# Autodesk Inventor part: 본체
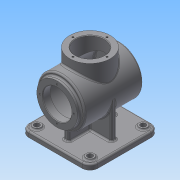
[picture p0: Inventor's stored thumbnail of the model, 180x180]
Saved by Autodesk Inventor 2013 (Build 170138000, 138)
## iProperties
Created: 2015-07
Part Number: 본체
Material: 일반
Document SubType Name: Modeling
Designer: Administrator
Density: 1 g/cm^3
Author: Administrator
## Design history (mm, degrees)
sketch "스케치1"
  geometry: L1 (-50, -65)-(50, -65); L2 (65, -50)-(65, 50); L3 (50, 65)-(-50, 65); L4 (-65, 50)-(-65, -50); L5 (-65, -65)-(65, 65); L6 (65, -65)-(-65, 65); C1 r 7.5 at (-50, 50); C2 r 7.5 at (50, 50); C3 r 7.5 at (-50, -50); C4 r 7.5 at (50, -50); A1 r 15 centre (-50, 50) between (-50, 65) and (-65, 50); A2 r 15 centre (-50, -50) between (-65, -50) and (-50, -65); A3 r 15 centre (50, -50) between (50, -65) and (65, -50); A4 r 15 centre (50, 50) between (65, 50) and (50, 65); 3 further points
  constraints: 12 end point, 8 centre point, 8 point on circle, 8 point on line, 8 tangent, 5 equal radius, 3 midpoint, 2 horizontal alignment, 2 parallel, 2 vertical alignment, 1 coincident, 1 horizontal, 1 perpendicular
  dimensions: "d0" = 130 distance of L5.end L6.end; "d2" = 130 distance of L6.start L5.end; "d3" = 15 radius of A1; "d4" = 15 diameter of C1; "d5" = 15 diameter of C2; "d6" = 100 distance of C2.centre C1.centre; "d7" = 50 horizontal distance of point (0, 0) C1.centre; "d8" = 100 distance of C3.centre C1.centre; "d9" = 50 horizontal distance of C1.centre point (0, 0)
extrude "돌출1" new body sketch "스케치1" distance "d10" = 10; taper "d11" = 0 deg
extrude "돌출2" join sketch "스케치1" distance "d12" = 3; taper "d13" = 0 deg
hole "구멍1" diameter "d16" = 10; stored, may be unused: countersink angle "d20" = 90 deg, drill point angle "d22" = 0 deg; dims "d14" = 10, "d15" = 10, "d17" = 6, "d18" = 4, "d19" = 2, "d21" = 8
hole "구멍2" diameter "d25" = 10; stored, may be unused: countersink angle "d29" = 90 deg, drill point angle "d31" = 0 deg; dims "d23" = 10, "d24" = 10, "d26" = 6, "d27" = 4, "d28" = 2, "d30" = 8
hole "구멍3" diameter "d34" = 10; stored, may be unused: countersink angle "d38" = 90 deg, drill point angle "d40" = 0 deg; dims "d32" = 10, "d33" = 10, "d35" = 6, "d36" = 4, "d37" = 2, "d39" = 8
hole "구멍4" diameter "d43" = 10; stored, may be unused: countersink angle "d47" = 90 deg, drill point angle "d49" = 0 deg; dims "d41" = 10, "d42" = 10, "d44" = 6, "d45" = 4, "d46" = 2, "d48" = 8
sketch "스케치2"
  geometry: L1 (50, -10)-(-50, -10) reference; C1 r 45 at (0, 68); 1 further point
  constraints: 1 centre point
  dimensions: "d51" = 90 diameter of C1; "d53" = 78 distance from line of C1.centre L1
extrude "돌출3" join sketch "스케치2" stored distance "d54" = 110; taper "d55" = 0 deg
sketch "스케치3"
  geometry: C1 r 45 at (0, 0) reference; C2 r 38 at (0, 0); 1 further point
  constraints: 1 centre point, 1 coincident
  dimensions: "d56" = 76 diameter of C2
extrude "돌출4" join sketch "스케치3" distance "d58" = 7; taper "d59" = 0 deg
hole "구멍5" diameter "d62" = 54; stored, may be unused: countersink angle "d66" = 90 deg, drill point angle "d68" = 0 deg; dims "d60" = 10, "d61" = 10, "d63" = 6, "d64" = 4, "d65" = 2, "d67" = 14
hole "구멍6" diameter "d71" = 80; stored, may be unused: countersink angle "d75" = 90 deg, drill point angle "d77" = 0 deg; dims "d69" = 10, "d70" = 10, "d72" = 6, "d73" = 4, "d74" = 2, "d76" = 96
node "작업 평면1"
sketch "스케치4"
  geometry: C1 r 38 at (0, 0); 1 further point
  constraints: 1 centre point, 1 coincident
  dimensions: "d79" = 76 diameter of C1
extrude "돌출5" join sketch "스케치4" stored distance "d81" = 7; taper "d82" = 0 deg
hole "구멍7" diameter "d85" = 54; stored, may be unused: countersink angle "d89" = 90 deg, drill point angle "d91" = 0 deg; dims "d83" = 10, "d84" = 10, "d86" = 6, "d87" = 4, "d88" = 2, "d90" = 43.25
sketch "스케치5"
  geometry: L1 (65, 50)-(65, -50) reference; L2 (-5, 5)-(-5, 45); L3 (-5, 45)-(5, 45); L4 (5, 45)-(5, 5); L5 (5, 5)-(45, 5); L6 (45, 5)-(45, -5); L7 (45, -5)-(5, -5); L8 (5, -5)-(5, -45); L9 (5, -45)-(-5, -45); L10 (-5, -45)-(-5, -5); L11 (-5, -5)-(-45, -5); L12 (-45, -5)-(-45, 5); L13 (-45, 5)-(-5, 5); 5 further points
  constraints: 24 end point, 9 parallel, 4 midpoint, 3 perpendicular, 2 horizontal alignment, 2 vertical alignment
  dimensions: "d92" = 10 distance of L2.end L3.end; "d94" = 10 distance of L5.end L6.end; "d95" = 10 distance of L8.end L9.end; "d96" = 10 distance of L11.end L12.end; "d97" = 90 distance between parallel lines of L6 L12; "d98" = 45 horizontal distance of point (0, 0) L12.end; "d99" = 90 distance between parallel lines of L9 L3; "d100" = 45 distance from line of L9 point (0, 0)
extrude "돌출6" join sketch "스케치5" stored distance "d101" = 7; taper "d102" = 0 deg
sketch "스케치6"
  geometry: C1 r 45 at (0, 0) reference; 2 further points
  constraints: 1 coincident, 1 other
feature "엠보싱1" sketch "스케치6" dims "d0" = 130, "d2" = 130, "d3" = 15, "d4" = 15, "d5" = 15, "d6" = 100, "d7" = 50, "d8" = 100, "d9" = 50, "d103" = 0.5, "d104" = 0
sketch "스케치7" dims "d105" = 64
  geometry: C1 r 27 at (0, 0) reference; C2 r 38 at (0, 0) reference; 3 further points
  constraints: 2 vertical alignment, 1 coincident, 2 other
hole "구멍8" sketch "스케치7" at (0, 32) diameter "d107" = 3.242; stored, may be unused: countersink angle "d111" = 90 deg, drill point angle "d113" = 118 deg; dims "d108" = 8, "d109" = 4, "d110" = 2, "d112" = 10
sketch "스케치8" dims "d117" = 64
  geometry: C1 r 38 at (0, 0) reference; C2 r 27 at (0, 0) reference; 2 further points
  constraints: 2 vertical alignment, 1 coincident, 2 other
hole "구멍9" sketch "스케치8" at (0, 32) diameter "d119" = 3.242; stored, may be unused: countersink angle "d123" = 90 deg, drill point angle "d125" = 118 deg; dims "d120" = 8, "d121" = 4, "d122" = 2, "d124" = 10
fillet "모깎기1" dims "d129" = 3
fillet "모깎기2" dims "d130" = 3
fillet "모깎기3" dims "d131" = 3
fillet "모깎기4" dims "d132" = 3
fillet "모깎기5" dims "d133" = 3
fillet "모깎기6" dims "d134" = 3
fillet "모깎기7" dims "d135" = 3
fillet "모깎기8" dims "d136" = 3
fillet "모깎기9" dims "d137" = 3
chamfer "모따기1" distance "d138" = 1; stored, may be unused: second distance "d139" = 2, angle "d140" = 45 deg
node "솔리드1"
pattern_circular "원형 패턴1" dims angle "d115" = 360 deg
pattern_circular "원형 패턴2" dims angle "d127" = 360 deg
